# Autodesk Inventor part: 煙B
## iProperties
Created: 2008-01
Part Number: 煙B
Document SubType Name: Modeling
Designer: t-ikumi
Density: 1 g/cm^3
Author: t-ikumi
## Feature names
1. ロフト2
2. シェル2
3. ロフト3
